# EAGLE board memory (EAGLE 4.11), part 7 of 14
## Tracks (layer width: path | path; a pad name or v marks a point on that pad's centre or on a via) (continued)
AND+TAD+ISZ  (via drill 0.61) (continued)
  Top 0.254: A08.J2 407.67,386.72 407.67,381.64 A08.L2 407.67,380.37 406.4,379.1 406.4,358.14 404.5,356.24 v404.5,346.71 | v428.62,272.42 v428.62,180.97 | v352.43,301.62 v352.43,278.13 | v368.94,345.44 368.3,344.81 v368.3,323.85
  Route2 0.254: v352.43,301.62 352.43,305.44 351.15,306.71 350.52,306.71 349.25,305.44 344.81,305.44 B13.N2
  Route3 0.254: v347.98,316.87 346.07,314.96 346.07,307.34 344.81,306.07 344.81,305.44 B13.N2
  Bottom 0.254: v428.62,180.97 433.07,180.97 D06.J2 | v428.62,272.42 426.08,274.96 403.86,274.96 403.23,275.59 384.81,275.59 384.18,274.96 382.27,274.96 380.37,276.86 366.39,276.86 365.76,277.5 353.06,277.5 v352.43,278.13 | v352.43,301.62 347.98,301.62 B13.P2 | v404.5,346.71 403.23,345.44 v368.94,345.44 | v368.3,323.85 367.67,323.22 365.12,323.22 363.86,321.95 354.96,321.95 354.33,322.58 353.69,322.58 v347.98,316.87
AND+TAD+OP1+JMP  (via drill 0.61)
  Top 0.254: F15.U2 321.94,15.88 319.4,13.34 F15.V2 318.77,12.06 318.77,9.52 317.5,8.25 314.32,8.25 v314.32,22.86 | v353.69,257.18 v357.5,253.36 | v295.27,189.86 295.27,207.64 292.1,210.82 v292.1,228.6
  Route2 0.254: v300.36,260.35 302.26,262.25 311.79,262.25 312.42,261.62 314.96,261.62 318.77,265.43 326.39,265.43 330.2,261.62 337.82,261.62 341,258.44 349.88,258.44 350.52,259.08 351.79,259.08 v353.69,257.18 | v357.5,253.36 358.14,252.73 365.76,252.73 367.03,251.46 369.57,251.46 C11.J2 | v293.37,104.77 v309.25,88.9
  Route3 0.254: v299.72,320.68 301.62,318.77 301.62,279.4 298.45,276.23 298.45,262.25 | 298.45,262.25 v300.36,260.35 | v314.32,22.86 315.6,24.13 315.6,26.67 314.32,27.94 314.32,58.42 308.61,64.13 308.61,65.41 307.98,66.04 307.98,87.63 v309.25,88.9 | v293.37,104.77 292.1,106.04 292.1,116.2 293.37,117.47 293.37,118.74 288.93,123.19 288.93,144.14 285.75,147.32 285.75,170.81 295.27,180.34 v295.27,189.86 | v292.1,228.6 295.27,228.6 295.27,245.11 296.55,246.38 298.45,246.38 298.45,262.25
  Bottom 0.254: v299.72,320.68 297.18,320.68 B17.H2
B_RUN
  Route3 0.254: F36.S2 55.24,22.86 53.98,24.13 53.98,67.31 44.45,76.83 44.45,90.17 43.18,91.44 E37.S2
BM  (via drill 0.61)
  Top 0.254: v224.79,90.8 225.43,91.44 v225.43,122.55 | v207.65,119.38 207.65,123.19 E24.E2
  Bottom 0.254: v224.79,90.8 219.07,90.8 217.81,89.53 E23.T2 | v225.43,122.55 215.26,122.55 214.63,121.92 213.36,121.92 212.09,123.19 208.28,123.19 E24.E2 | v207.65,119.38 200.66,112.39 194.31,112.39 187.96,106.04 179.07,106.04 175.26,109.85 166.37,109.85 162.56,106.04 156.84,106.04 156.21,106.68 150.5,106.68 149.86,106.04 140.97,106.04 137.16,109.85 134.62,109.85 133.99,109.22 125.09,109.22 124.46,109.85 121.92,109.85 121.28,109.22 112.39,109.22 111.76,109.85 109.22,109.85 108.58,109.22 99.69,109.22 99.06,109.85 90.17,109.85 83.19,102.87 74.3,102.87 70.48,106.68 61.59,106.68 60.96,106.04 53.98,106.04 52.7,107.31 E36.L2
BMA0
  Bottom 0.254: F29.D2 141.6,57.79 142.88,59.05 149.86,59.05 150.5,58.42 159.38,58.42 160.02,59.05 162.56,59.05 163.19,58.42 172.09,58.42 172.72,59.05 175.26,59.05 175.9,58.42 184.78,58.42 185.42,59.05 187.96,59.05 188.59,58.42 197.49,58.42 198.12,59.05 199.39,59.05 201.29,57.15 204.47,57.15 F24.D2
BMA1
  Bottom 0.254: F29.E2 144.78,53.34 145.41,52.7 149.86,52.7 150.5,52.07 159.38,52.07 160.02,52.7 162.56,52.7 163.19,52.07 172.09,52.07 172.72,52.7 175.26,52.7 175.9,52.07 184.78,52.07 185.42,52.7 187.96,52.7 188.59,52.07 197.49,52.07 198.12,52.7 200.66,52.7 201.93,51.44 204.47,51.44 F24.F2
BMA2
  Bottom 0.254: F29.H2 144.78,46.99 145.41,46.36 149.86,46.36 150.5,45.72 159.38,45.72 160.02,46.36 162.56,46.36 163.19,45.72 172.09,45.72 172.72,46.36 175.26,46.36 175.9,45.72 184.78,45.72 185.42,46.36 187.96,46.36 188.59,45.72 197.49,45.72 198.12,46.36 199.39,46.36 200.66,45.09 204.47,45.09 F24.J2
BMA3
  Bottom 0.254: F29.K2 144.78,40.64 145.41,40.01 149.86,40.01 150.5,39.37 159.38,39.37 160.02,40.01 162.56,40.01 163.19,39.37 172.09,39.37 172.72,40.01 175.26,40.01 175.9,39.37 184.78,39.37 185.42,40.01 187.96,40.01 188.59,39.37 197.49,39.37 198.12,40.01 200.66,40.01 201.93,38.73 204.47,38.73 F24.L2
BMA4
  Bottom 0.254: F29.M2 144.78,34.29 145.41,33.66 149.86,33.66 150.5,33.02 159.38,33.02 160.02,33.66 162.56,33.66 163.19,33.02 172.09,33.02 172.72,33.66 175.26,33.66 175.9,33.02 184.78,33.02 185.42,33.66 187.96,33.66 188.59,33.02 197.49,33.02 198.12,33.66 200.66,33.66 201.93,32.38 204.47,32.38 F24.N2
BMA5
  Bottom 0.254: F29.P2 144.78,27.94 145.41,27.3 149.86,27.3 150.5,26.67 159.38,26.67 160.02,27.3 162.56,27.3 163.19,26.67 172.09,26.67 172.72,27.3 175.26,27.3 175.9,26.67 184.78,26.67 185.42,27.3 187.96,27.3 188.59,26.67 197.49,26.67 198.12,27.3 200.66,27.3 201.93,26.03 204.47,26.03 F24.R2
BMA6  (via drill 0.61)
  Top 0.254: v146.05,4.44 146.05,20.32 144.78,21.59 F29.S2 | v206.38,5.08 206.38,17.14 205.1,18.41 F24.T2
  Bottom 0.254: v146.05,4.44 147.32,3.17 194.31,3.17 196.22,5.08 v206.38,5.08
BMA7  (via drill 0.61)
  Top 0.254: v139.7,50.16 139.7,20.95 140.97,19.69 F29.T2
  Bottom 0.254: v139.7,50.16 139.7,55.25 149.86,55.25 150.5,55.88 159.38,55.88 160.02,55.25 162.56,55.25 163.19,55.88 172.09,55.88 172.72,55.25 175.26,55.25 175.9,55.88 184.78,55.88 185.42,55.25 187.96,55.25 189.23,56.52 191.77,56.52 F25.D2
BMA8  (via drill 0.61)
  Top 0.254: v180.97,13.34 180.97,16.51 184.15,19.69 184.15,23.49 182.25,25.4 186.69,29.84 187.96,29.84 190.5,32.38 190.5,45.72 192.41,47.62 192.41,50.16 F25.F2
  Bottom 0.254: v180.97,13.34 182.25,13.34 182.25,12.06 180.97,10.79 172.72,10.79 172.09,11.43 164.47,11.43 163.83,10.79 142.88,10.79 141.6,12.06 F29.V2
BMA9  (via drill 0.61)
  Top 0.254: v127,45.72 127,55.25 128.27,56.52 F30.D2
  Bottom 0.254: v127,45.72 127,40.01 133.35,40.01 136.53,43.18 146.69,43.18 147.32,42.55 149.86,42.55 150.5,43.18 159.38,43.18 160.02,42.55 162.56,42.55 163.19,43.18 172.09,43.18 172.72,42.55 175.26,42.55 175.9,43.18 184.78,43.18 185.42,42.55 187.96,42.55 189.23,43.82 191.77,43.82 F25.J2
BMA10
  Bottom 0.254: F30.E2 131.44,53.34 131.44,49.53 129.54,49.53 123.83,43.82 123.83,36.83 133.99,36.83 134.62,36.2 137.16,36.2 137.79,36.83 146.69,36.83 147.32,36.2 149.86,36.2 150.5,36.83 159.38,36.83 160.02,36.2 162.56,36.2 163.19,36.83 172.09,36.83 172.72,36.2 175.26,36.2 175.9,36.83 184.78,36.83 185.42,36.2 186.69,36.2 187.96,37.46 191.77,37.46 F25.L2
BMA11  (via drill 0.61)
  Top 0.254: v138.43,31.75 133.35,36.83 133.35,45.72 132.08,46.99 F30.H2
  Bottom 0.254: v138.43,31.75 140.34,29.84 149.86,29.84 150.5,30.48 159.38,30.48 160.02,29.84 162.56,29.84 163.19,30.48 172.09,30.48 172.72,29.84 175.26,29.84 175.9,30.48 184.78,30.48 185.42,29.84 187.96,29.84 189.23,31.12 191.77,31.12 F25.N2
BMB03  (via drill 0.61)
  Route3 0.254: v49.53,146.69 50.8,147.95 50.8,208.28 49.53,209.55 49.53,212.09 50.16,212.72 50.16,220.98 50.8,221.61 50.8,276.86 48.9,278.77 48.9,287.02 47.62,288.29 47.62,322.58 v48.9,323.85
  Bottom 0.254: v49.53,146.69 48.26,145.41 16.51,145.41 15.88,146.05 0.64,146.05 0.64,144.78 13.34,132.08 15.88,132.08 15.88,126.36 5.71,116.2 5.08,116.2 5.08,111.76 E40.K2 | v48.9,323.85 46.99,325.75 41.27,325.75 40.01,324.49 B37.F2
BMB04  (via drill 0.61)
  Route2 0.254: v5.08,161.29 6.35,161.29 6.35,104.14 5.71,103.5 5.08,103.5 5.08,99.06 E40.P2
  Route3 0.254: v5.08,161.29 3.17,163.19 3.17,193.04 6.35,196.22 v6.35,278.13 | v39.37,288.93 41.27,290.83 41.27,309.25 40.01,310.52 B37.L2
  Bottom 0.254: v6.35,278.13 6.99,278.77 11.43,278.77 20.32,287.66 22.86,287.66 23.5,287.02 32.38,287.02 33.02,287.66 35.56,287.66 36.2,287.02 37.47,287.02 v39.37,288.93
BMB05  (via drill 0.61)
  Top 0.254: v36.2,257.81 38.1,259.72 38.1,294 39.37,295.28 39.37,297.81 B37.R2
  Route3 0.254: v5.08,147.32 3.17,145.41 3.17,90.8 1.91,89.53 E40.T2 | v17.14,155.57 19.05,157.48 19.05,226.69 25.4,233.04 25.4,249.56 v24.13,250.82
  Bottom 0.254: v5.08,147.32 8.26,147.32 16.51,155.57 v17.14,155.57 | v24.13,250.82 28.57,255.27 33.66,255.27 v36.2,257.81
BMB06  (via drill 0.61)
  Route2 0.254: v125.73,387.35 127.64,389.25 137.16,389.25 140.97,385.45 149.86,385.45 156.21,391.8 162.56,391.8 163.19,392.43 172.09,392.43 172.72,391.8 175.26,391.8 175.9,392.43 182.25,392.43 191.77,401.96 200.66,401.96 201.29,401.32 210.19,401.32 220.34,411.48 235.59,411.48 245.11,401.96 251.46,401.96 252.09,401.32 260.99,401.32 261.62,401.96 264.16,401.96 264.8,401.32 273.69,401.32 277.5,405.13 286.38,405.13 290.83,400.69 293.37,400.69 A17.D2
  Route3 0.254: v93.34,231.78 95.25,233.68 95.25,290.83 92.08,294 92.08,347.35 117.47,372.75 117.47,379.1 v125.73,387.35
  Bottom 0.254: v93.34,231.78 88.27,226.69 87,226.69 86.36,227.33 77.47,227.33 70.48,220.34 61.59,220.34 60.96,220.98 58.42,220.98 57.78,220.34 51.44,220.34 48.26,217.17 20.95,217.17 2.54,198.75 1.27,198.75 1.27,194.31 D40.D2
BMB07  (via drill 0.61)
  Top 0.254: v267.97,410.21 268.61,410.85 268.61,415.29 272.42,419.1 301.62,419.1 301.62,414.66 309.88,406.4 v309.88,405.13 | v314.96,393.7 317.5,391.16 v317.5,383.54
  Route2 0.254: v180.97,408.94 180.97,411.48 190.5,411.48 v191.77,410.21
  Route3 0.254: v127,186.69 127,239.39 128.27,240.66 128.27,242.57 127,243.84 127,261.62 125.73,262.89 125.73,264.8 127,266.06 127,270.51 126.36,271.15 126.36,271.78 127,272.42 127,307.34 136.53,316.87 136.53,353.7 146.05,363.22 146.05,369.57 154.94,378.46 154.94,379.73 180.97,405.77 v180.97,408.94 | v309.88,405.13 311.15,403.86 311.15,397.51 v314.96,393.7 | v317.5,383.54 300.36,366.4 299.72,366.4 v297.18,368.94
  Bottom 0.254: v127,186.69 125.73,186.69 123.83,184.78 121.28,184.78 120.65,185.42 116.84,185.42 113.67,182.25 112.39,182.25 111.76,182.88 109.22,182.88 108.58,182.25 99.69,182.25 95.89,186.06 87,186.06 83.19,182.25 74.3,182.25 73.66,182.88 71.12,182.88 70.48,182.25 61.59,182.25 60.96,182.88 58.42,182.88 57.78,182.25 48.9,182.25 48.26,182.88 45.72,182.88 45.09,182.25 36.2,182.25 35.56,182.88 26.67,182.88 22.86,179.07 13.97,179.07 10.16,182.88 5.71,182.88 5.08,183.51 D40.H2 | v191.77,410.21 192.41,410.85 197.49,410.85 198.12,411.48 199.39,411.48 200.66,412.75 248.28,412.75 249.56,411.48 266.06,411.48 267.33,410.21 v267.97,410.21 | v297.18,368.94 294,368.94 A17.R2
BMB08  (via drill 0.61)
  Top 0.254: v238.12,410.21 238.12,396.24 v240.66,393.7 | v299.72,372.75 301.62,370.84 301.62,365.76 v300.99,365.12
  Route2 0.254: v157.48,419.1 155.57,419.1 154.94,419.74 149.22,419.74 145.41,415.93 46.35,415.93 9.53,379.1 6.35,379.1 6.35,307.34 3.17,304.17 3.17,280.04 6.35,276.86 6.35,247.01 2.54,243.2 2.54,240.03 6.35,236.22 6.35,189.86 5.71,189.23 3.17,189.23 3.17,175.26 4.45,173.99 4.45,172.09 D40.M2
  Route3 0.254: v157.48,419.1 161.93,414.66 193.04,414.66 194.31,413.39 238.12,413.39 v238.12,410.21 | v240.66,393.7 241.94,394.97 247.65,394.97 247.65,393.06 257.81,382.91 264.16,382.91 264.8,382.27 273.69,382.27 274.32,382.91 276.86,382.91 277.5,382.27 286.38,382.27 287.02,382.91 289.56,382.91 v299.72,372.75 | v300.99,365.12 297.18,361.31 294,361.31 A17.T2
BPAR
  Route3 0.254: F36.V2 52.07,13.34 50.8,14.61 50.8,69.22 41.27,78.74 41.27,86.99 40.01,88.27 E37.T2
BT00  (via drill 0.61)
  Top 0.254: E09.H2 398.14,118.11 398.14,123.19 E09.E2 | 196.85,299.72 196.85,288.29 195.58,287.02 v195.58,276.23 195.58,274.96 196.85,273.69 v196.85,118.74 196.85,85.09 195.58,83.82 195.58,81.91 196.85,80.64 196.85,17.78 195.58,16.51 F25.U2 | 196.85,299.72 195.58,300.99 B25.P2 | v139.7,276.23 139.7,309.25 140.97,310.52 B29.L2 | 196.85,299.72 196.85,318.77 195.58,320.04 B25.H2 | v203.2,361.95 203.2,398.15 204.47,399.42 A24.D2
  Route2 0.254: v372.75,113.66 372.11,113.03 364.49,113.03 358.14,106.68 351.79,106.68 347.98,102.87 339.09,102.87 335.28,106.68 326.39,106.68 325.75,106.04 325.12,106.04 324.49,106.68 313.69,106.68 313.06,106.04 304.17,106.04 297.18,113.03 288.29,113.03 287.65,112.39 285.12,112.39 v284.48,113.03
  Route3 0.254: v203.2,361.95 201.93,360.68 203.2,359.41 203.2,331.47 195.58,323.85 195.58,321.31 B25.H2 | v255.27,112.39 251.46,116.2 v248.92,116.2
  Bottom 0.254: v195.58,276.23 v139.7,276.23 | v372.75,113.66 374.01,113.66 375.29,112.39 376.56,112.39 378.46,114.3 379.1,114.3 381,112.39 389.25,112.39 389.89,113.03 398.14,113.03 398.14,116.84 E09.H2 | v284.48,113.03 275.59,113.03 274.95,112.39 267.33,112.39 266.06,113.66 264.16,113.66 262.89,112.39 v255.27,112.39 | v248.92,116.2 248.28,115.57 237.49,115.57 233.68,119.38 224.79,119.38 224.16,118.74 215.26,118.74 214.63,119.38 212.09,119.38 211.46,118.74 209.55,118.74 207.65,120.65 207.01,120.65 205.74,119.38 199.39,119.38 198.75,118.74 v196.85,118.74
BT12  (via drill 0.61)
  Top 0.254: v245.11,323.85 245.75,324.49 245.75,326.39 B21.E2
  Route2 0.254: v99.69,309.88 96.52,306.71 92.08,306.71 90.81,305.44 B33.N2 | v147.96,314.33 149.86,316.23 159.38,316.23 160.02,315.6 162.56,315.6 163.19,316.23 172.09,316.23 172.72,315.6 175.26,315.6 175.9,316.23 184.78,316.23 185.42,315.6 187.96,315.6 188.59,316.23 197.49,316.23 201.29,312.42 210.19,312.42 217.17,319.41 226.06,319.41 226.69,318.77 227.33,318.77 228.6,320.04 231.78,320.04 232.41,319.41 238.76,319.41 239.4,318.77 240.03,318.77 v245.11,323.85
  Bottom 0.254: v99.69,309.88 108.58,309.88 109.22,309.25 111.76,309.25 115.57,313.06 124.46,313.06 125.09,312.42 133.99,312.42 134.62,313.06 137.16,313.06 137.79,312.42 146.05,312.42 v147.96,314.33
BT(00-06)  (via drill 0.61)
  Route2 0.254: v300.36,314.33 302.26,312.42 311.79,312.42 312.42,313.06 313.69,313.06 318.13,308.61 321.94,308.61 B15.M2
  Route3 0.254: v233.04,374.02 231.78,372.75 v231.78,372.11 | v271.78,367.67 273.05,366.4 273.05,353.7 274.32,352.43 274.32,338.46 273.05,337.19 273.05,328.3 v284.48,316.87
  Bottom 0.254: v233.04,374.02 231.14,375.92 226.69,375.92 226.06,376.56 223.52,376.56 222.88,375.92 214,375.92 210.82,379.1 206.38,379.1 205.1,380.37 A24.L2 | v231.78,372.11 231.78,370.21 238.76,370.21 239.4,369.57 248.28,369.57 248.92,370.21 251.46,370.21 252.09,369.57 260.99,369.57 261.62,370.21 264.16,370.21 264.8,369.57 269.88,369.57 v271.78,367.67 | v284.48,316.87 285.75,315.6 289.56,315.6 290.19,316.23 291.46,316.23 294.64,313.06 298.45,313.06 299.72,314.33 v300.36,314.33
BT(07-11)  (via drill 0.61)
  Top 0.254: v393.7,245.11 393.7,241.94 394.97,240.66 394.97,238.76 C09.N2
  Bottom 0.254: v393.7,245.11 392.43,245.11 391.16,246.38 386.71,246.38 386.08,247.01 C10.K2
C  (via drill 0.61)
  Route2 0.254: v165.74,344.17 167,345.44 186.69,345.44 187.32,344.81 219.07,344.81 220.34,346.08 254.63,346.08 255.27,345.44 259.71,345.44 v261.62,347.35
  Route3 0.254: v165.74,344.17 161.93,340.36 161.93,310.52 158.75,307.34 158.75,303.53 157.48,302.26 B28.P2 | v261.62,347.35 262.89,348.62 262.89,354.33 269.88,361.31 269.88,367.03 274.32,371.48 v274.95,371.48
  Bottom 0.254: v274.95,371.48 276.86,373.38 286.38,373.38 287.02,372.75 289.56,372.75 290.83,374.02 293.37,374.02 A17.N2
CA  (via drill 0.61)
  Top 0.254: A22.L2 230.5,381.64 231.78,382.91 231.78,391.8 230.5,393.06 A22.F2 | v160.66,279.4 160.66,281.31 154.31,287.66 154.31,291.47 B28.T2 | 206.38,315.6 v206.38,279.4 | 206.38,315.6 205.1,316.87 B24.J2 | 206.38,315.6 206.38,325.12 207.65,326.39 B24.E2
  Route2 0.254: v224.16,377.83 226.06,379.73 229.24,379.73 229.87,380.37 A22.L2
  Route3 0.254: v224.16,377.83 212.72,366.4 212.72,357.5 215.26,354.97 215.26,342.9 209.55,337.19 209.55,328.93 208.28,327.66 B24.E2
  Bottom 0.254: v160.66,279.4 161.93,280.67 197.49,280.67 198.75,279.4 v206.38,279.4
CLL  (via drill 0.61)
  Top 0.254: v396.88,22.86 396.88,29.21 405.13,37.46 407.67,37.46 F08.L2 | v217.17,241.94 215.9,240.66 215.9,235.59 217.17,234.31 217.17,233.68 215.9,232.41 215.9,224.79 217.81,222.88 v217.81,220.98 | v125.73,168.28 123.83,166.37 123.83,147.95 122.56,146.69 v122.56,136.53 | v182.88,75.56 184.15,74.29 v184.15,53.98
  Route2 0.254: v214.63,208.91 214,209.55 201.93,209.55 199.39,212.09 186.69,212.09 181.61,207.01 156.84,207.01 142.24,192.41 137.79,192.41 v128.27,182.88 | v122.56,136.53 130.18,128.91 130.18,125.73 129.54,125.73 124.46,120.65 124.46,119.38 127.64,119.38 167.64,79.38 179.07,79.38 v182.88,75.56 | v184.15,53.98 184.78,53.34 187.32,53.34 194.31,46.36 200.66,46.36 204.47,42.55 213.36,42.55 214,43.18 222.88,43.18 229.87,36.2 238.76,36.2 239.4,36.83 248.28,36.83 252.09,33.02 260.99,33.02 261.62,33.66 264.16,33.66 265.43,32.38 267.97,32.38 F19.N2
  Route3 0.254: v278.76,25.4 273.05,31.12 273.05,31.75 268.61,31.75 F19.N2 | v309.88,26.67 311.15,25.4 311.15,24.13 v313.06,22.23 | v217.17,241.94 219.07,243.84 219.07,249.56 228.6,259.08 228.6,274.96 231.14,277.5 231.14,280.67 228.6,283.21 228.6,300.36 231.78,303.53 231.78,353.06 244.47,365.76 244.47,382.27 245.75,383.54 A21.K2 | v217.81,220.98 219.07,219.71 219.07,216.53 214.63,212.09 v214.63,208.91 | v128.27,182.88 127,181.61 127,169.54 v125.73,168.28
  Bottom 0.254: v278.76,25.4 280.04,24.13 283.85,24.13 287.02,27.3 289.56,27.3 290.19,26.67 299.08,26.67 299.72,27.3 302.26,27.3 302.89,26.67 v309.88,26.67 | v313.06,22.23 314.96,20.32 324.49,20.32 325.12,20.95 326.39,20.95 328.93,18.41 330.2,18.41 331.47,17.14 340.36,17.14 341,17.78 349.88,17.78 350.52,17.14 353.06,17.14 353.69,17.78 362.58,17.78 363.22,17.14 365.76,17.14 366.39,17.78 375.29,17.78 375.92,17.14 378.46,17.14 379.1,17.78 387.99,17.78 388.62,17.14 389.89,17.14 395.61,22.86 v396.88,22.86
CLR_AC  (via drill 0.61)
  Top 0.254: v363.86,79.38 363.22,78.74 v363.22,71.75 | v250.82,24.77 236.85,10.79 233.68,10.79 233.68,15.24 F22.U2
  Route2 0.254: v99.69,25.4 44.45,80.64 44.45,97.79 43.18,97.79 E37.P2 | v363.86,79.38 370.84,79.38 375.92,84.45 377.82,84.45 381.63,80.64 406.4,80.64 406.4,97.79 421.64,113.03 425.45,113.03 425.45,127.63 432.44,134.62 433.07,134.62 433.07,143.51 434.98,145.41 434.98,149.86 434.34,150.5 433.7,150.5 433.7,154.94 D06.T2 | v363.22,71.75 361.31,69.85 342.26,69.85 341.63,70.48 302.89,70.48 v296.55,64.13
  Route3 0.254: v296.55,64.13 282.57,50.16 282.57,43.82 281.94,43.18 275.59,43.18 274.95,42.55 266.7,42.55 266.7,40.64 v250.82,24.77
  Bottom 0.254: v99.69,25.4 104.14,20.95 109.86,20.95 113.67,17.14 122.56,17.14 123.19,17.78 125.73,17.78 126.36,17.14 135.25,17.14 135.89,17.78 138.43,17.78 139.06,17.14 147.96,17.14 148.59,17.78 151.13,17.78 151.76,17.14 160.66,17.14 164.47,20.95 173.35,20.95 173.99,20.32 176.53,20.32 177.16,20.95 186.06,20.95 186.69,20.32 189.23,20.32 189.87,20.95 198.75,20.95 199.39,20.32 201.93,20.32 202.56,20.95 211.46,20.95 212.09,20.32 214.63,20.32 215.26,20.95 224.16,20.95 224.79,20.32 234.95,20.32 234.95,17.78 233.68,16.51 F22.U2
CM
  Top 0.254: E24.P2 207.65,99.06 206.38,100.33 206.38,109.22 205.1,110.49 205.1,113.66 E24.J2
CML  (via drill 0.61)
  Top 0.254: v222.25,294 v222.25,311.15 | v243.21,289.56 244.47,288.29 244.47,154.31 243.21,153.03 v243.21,152.4 | v292.1,144.14 292.1,125.09 295.27,121.92 295.27,116.2 v296.55,114.93 | v328.3,81.28 330.2,79.38 330.2,60.96 v332.11,59.05 | v346.71,46.36 346.07,46.99 346.07,52.07 344.81,53.34 344.81,56.52 F13.D2
  Route2 0.254: v222.25,311.15 217.81,311.15 B23.L2 | v243.21,152.4 249.56,146.05 287.65,146.05 289.56,144.14 v292.1,144.14
  Route3 0.254: v300.36,111.12 301.62,109.85 301.62,84.45 v303.53,82.55 | v367.03,45.09 v369.57,42.55
  Bottom 0.254: v222.25,294 226.06,294 226.69,293.37 235.59,293.37 236.22,294 237.49,294 241.94,289.56 v243.21,289.56 | v296.55,114.93 v300.36,111.12 | v303.53,82.55 304.8,81.28 311.79,81.28 312.42,80.64 327.66,80.64 v328.3,81.28 | v332.11,59.05 339.09,59.05 341,57.15 344.17,57.15 F13.D2 | v369.57,42.55 376.56,42.55 377.19,43.18 379.73,43.18 380.37,42.55 389.25,42.55 389.89,43.18 392.43,43.18 393.06,42.55 401.95,42.55 402.59,43.18 405.13,43.18 405.76,42.55 410.21,42.55 410.85,41.91 F08.K2 | v367.03,45.09 365.76,46.36 354.96,46.36 354.33,45.72 351.79,45.72 351.15,46.36 v346.71,46.36
DC  (via drill 0.61)
  Top 0.254: v82.55,293.37 82.55,318.77 83.82,320.04 v83.82,320.68 | v78.74,341.63 79.38,342.27 79.38,366.4 78.11,367.67 A34.R2 | v370.2,182.88 369.57,183.51 369.57,185.42 365.12,189.86 v365.12,216.53 | v322.58,257.81 320.68,259.72 320.68,266.06 311.15,275.59 v311.15,288.93 | v114.94,290.83 122.56,283.21 v122.56,274.96 | v186.69,278.13 190.5,274.32 v190.5,256.54
  Route2 0.254: v82.55,293.37 82.55,287.66 86.36,287.66 90.81,283.21 104.14,283.21 111.76,290.83 v114.94,290.83 | v122.56,274.96 125.73,278.13 177.16,278.13 178.44,279.4 185.42,279.4 v186.69,278.13 | v190.5,256.54 191.77,255.27 200.66,255.27 204.47,259.08 213.36,259.08 214,258.44 222.88,258.44 223.52,259.08 224.79,259.08 228.6,255.27 234.95,255.27 238.12,252.09 248.28,252.09 255.27,259.08 264.16,259.08 267.97,255.27 276.86,255.27 280.67,259.08 288.93,259.08 292.1,255.91 295.27,255.91 297.18,257.81 302.89,252.09 303.53,252.09 v306.07,254.63
  Route3 0.254: v83.82,320.68 82.55,321.95 82.55,335.92 78.74,339.73 v78.74,341.63 | v325.75,221.61 323.85,223.52 323.85,256.54 v322.58,257.81 | v311.15,288.93 311.15,306.07 309.88,307.34 B16.M2
  Bottom 0.254: v82.55,293.37 74.3,293.37 73.66,294 66.67,294 65.41,292.74 B35.T2 | v370.2,182.88 376.56,182.88 380.37,179.07 389.25,179.07 390.52,180.34 393.06,180.34 394.33,179.07 401.95,179.07 402.59,179.7 405.13,179.7 405.76,179.07 414.65,179.07 415.93,180.34 420.37,180.34 D07.J2 | v365.12,216.53 351.15,216.53 350.52,217.17 336.55,217.17 334.01,219.71 334.01,220.98 329.56,220.98 328.93,220.34 327.02,220.34 v325.75,221.61 | v306.07,254.63 309.88,258.44 311.79,258.44 312.42,259.08 314.96,259.08 315.6,258.44 321.94,258.44 v322.58,257.81
DCA  (via drill 0.61)
  Top 0.254: v235.59,46.36 234.95,46.99 234.95,61.59 v233.04,63.5 | v229.87,65.41 229.87,79.38 225.43,83.82 225.43,88.27 228.6,91.44 228.6,139.06 225.43,142.24 v225.43,210.19 | v434.98,208.91 434.98,273.05 428.62,279.4 v428.62,365.12
  Route2 0.254: v233.04,63.5 231.14,65.41 v229.87,65.41 | v428.62,365.12 427.36,366.4 420.37,366.4 416.56,370.21 410.21,370.21 398.14,382.27 391.8,382.27 388.62,385.45 384.18,385.45 382.9,386.72 A10.J2
  Bottom 0.254: v235.59,46.36 236.85,46.36 240.03,43.18 246.38,43.18 250.19,39.37 254.63,39.37 255.27,38.73 F20.L2 | v225.43,210.19 234.31,210.19 235.59,211.45 314.96,211.45 315.6,210.82 332.11,210.82 332.74,210.19 380.37,210.19 381,209.55 431.17,209.55 431.8,208.91 v434.98,208.91 | v428.62,365.12 428.62,369.57 431.8,369.57 433.7,371.48 436.25,371.48 A06.P2
DF0  (via drill 0.61)
  Top 0.254: v368.3,12.06 360.68,4.44 341.63,4.44 v341.63,12.7 | v338.45,15.88 336.55,15.88 336.55,14.61 333.38,11.43 333.38,9.52 326.39,2.54 326.39,1.27 292.74,1.27 v292.74,5.71 | v252.09,5.71 250.82,4.44 235.59,4.44 235.59,5.71 231.78,9.52 v230.5,9.52
  Route2 0.254: v389.25,7.62 390.52,8.89 391.8,8.89 392.43,8.25 456.56,8.25 478.79,30.48 487.05,30.48 487.05,34.29 F02.M2
  Route3 0.254: v389.25,7.62 388.62,8.25 388.62,8.89 386.71,10.79 368.3,10.79 v368.3,12.06 | v341.63,12.7 v338.45,15.88 | v292.74,5.71 287.02,5.71 285.12,7.62 252.09,7.62 v252.09,5.71 | v230.5,9.52 229.24,8.25 206.38,8.25 206.38,13.97 165.1,55.25 165.1,67.31 149.22,83.18 149.22,91.44 142.88,97.79 142.88,102.23 v140.97,104.14
  Bottom 0.254: v140.97,104.14 138.43,106.68 135.89,106.68 135.25,106.04 126.36,106.04 125.73,106.68 123.19,106.68 121.92,105.41 119.38,105.41 E31.M2
DF1  (via drill 0.61)
  Top 0.254: v187.96,31.12 187.32,31.75 v187.32,74.93
  Route2 0.254: v187.96,31.12 188.59,31.12 189.87,29.84 198.75,29.84 199.39,30.48 201.93,30.48 202.56,29.84 211.46,29.84 212.09,30.48 214.63,30.48 215.26,29.84 224.16,29.84 224.79,30.48 227.33,30.48 227.97,29.84 236.85,29.84 237.49,30.48 246.38,30.48 247.65,29.21 248.92,29.21 251.46,26.67 255.91,26.67 256.54,27.3 263.52,27.3 267.33,23.49 274.95,23.49 278.76,27.3 287.65,27.3 288.29,26.67 290.83,26.67 291.46,27.3 300.36,27.3 300.99,26.67 307.34,26.67 310.51,23.49 313.69,23.49 317.5,27.3 325.75,27.3 332.11,20.95 338.45,20.95 339.09,20.32 341.63,20.32 342.26,20.95 351.15,20.95 351.79,20.32 354.33,20.32 354.96,20.95 363.86,20.95 364.49,20.32 372.11,20.32 375.29,17.14 376.56,17.14 377.19,17.78 386.08,17.78 389.89,13.97 392.43,13.97 393.06,14.61 402.59,14.61 406.4,10.79 454.02,10.79 480.06,36.83 483.24,36.83 483.87,37.46 F02.L2 | v187.32,74.93 186.69,74.29 179.71,74.29 175.26,78.74 140.97,78.74 121.92,97.79 119.38,97.79 E31.P2
DF2  (via drill 0.61)
  Top 0.254: v125.73,120.65 123.83,118.74 123.83,99.69 119.38,95.25 119.38,92.71 E31.S2
  Route2 0.254: v363.22,28.58 363.86,28.58 365.76,26.67 367.03,26.67 367.67,27.3 376.56,27.3 377.19,26.67 387.35,26.67 391.16,30.48 400.05,30.48 403.86,26.67 411.48,26.67 415.29,30.48 424.81,30.48 428.62,26.67 436.88,26.67 440.69,30.48 449.58,30.48 453.39,26.67 464.19,26.67 473.71,36.2 478.15,36.2 481.33,39.37 485.77,39.37 487.05,40.64 F02.K2 | v321.94,57.15 317.5,61.59 317.5,67.94 316.87,67.94 316.23,68.58 307.34,68.58 v306.07,67.31 | v284.48,88.9 v274.95,98.42 | v236.22,93.34 235.59,93.98 228.6,93.98 219.71,102.87 212.09,102.87 198.75,116.2 194.31,116.2 170.81,139.7 145.41,139.7 126.36,120.65 v125.73,120.65
  Route3 0.254: v363.22,28.58 361.31,30.48 351.79,30.48 351.15,29.84 342.26,29.84 330.2,41.91 330.2,48.9 v321.94,57.15 | v306.07,67.31 290.83,82.55 288.93,82.55 288.93,83.82 284.48,88.27 v284.48,88.9
  Bottom 0.254: v274.95,98.42 273.05,100.33 262.89,100.33 262.25,99.69 253.37,99.69 252.73,100.33 251.46,100.33 245.11,93.98 237.49,93.98 236.85,93.34 v236.22,93.34
DM  (via drill 0.61)
  Top 0.254: v201.29,121.92 203.2,120.02 203.2,94.61 204.47,93.34 204.47,89.53 E24.T2 | 53.98,122.55 53.98,191.77 52.7,193.04 D36.D2 | 53.98,122.55 53.98,97.16 52.7,95.88 E36.R2 | v54.61,122.55 53.98,122.55
  Bottom 0.254: v201.29,121.92 200.03,123.19 195.58,123.19 E25.E2 194.94,123.19 193.68,121.92 186.69,121.92 182.88,125.73 173.99,125.73 170.18,121.92 161.29,121.92 160.66,122.55 151.76,122.55 147.96,118.74 139.06,118.74 135.25,122.55 133.99,122.55 133.35,121.92 123.19,121.92 122.56,122.55 118.11,122.55 117.47,121.92 110.49,121.92 106.68,125.73 97.79,125.73 93.98,121.92 85.09,121.92 84.45,122.55 75.56,122.55 74.93,121.92 72.39,121.92 71.75,122.55 62.87,122.55 62.23,121.92 59.69,121.92 59.05,122.55 v54.61,122.55
EM  (via drill 0.61)
  Top 0.254: v57.15,74.29 57.15,83.82 55.88,85.09 E36.U2 | v190.5,73.02 v190.5,93.98 | E25.J2 192.41,113.66 193.68,112.39 193.68,100.33 194.94,99.06 E25.P2
  Bottom 0.254: v57.15,74.29 59.05,72.39 145.41,72.39 146.05,73.02 v190.5,73.02 | v190.5,93.98 190.5,97.79 194.94,97.79 E25.P2
EX+DC  (via drill 0.61)
  Top 0.254: v313.06,143.51 313.69,142.88 313.69,135.89 v313.06,135.25 | v344.17,117.47 344.17,114.93 E13.J2 | B25.E2 194.94,326.39 194.94,324.49 193.04,322.58 193.04,318.77 192.41,318.14 B25.J2 191.77,316.87 v191.77,314.96 | B33.H2 93.34,321.31 93.34,326.39 B33.E2 | v230.5,260.99 225.43,266.06 225.43,270.51 v217.81,278.13
  Route2 0.254: v309.88,186.69 307.98,188.59 302.89,188.59 299.72,191.77 295.27,191.77 294,193.04 D17.D2 | v313.06,135.25 313.69,134.62 321.94,134.62 328.3,128.27 337.19,128.27 337.82,128.91 338.45,128.91 346.71,120.65 v347.35,120.65 | v155.57,321.95 154.94,322.58 148.59,322.58 147.96,321.95 139.06,321.95 138.43,322.58 135.89,322.58 135.25,321.95 126.36,321.95 122.56,325.75 113.67,325.75 109.86,321.95 100.97,321.95 100.33,322.58 97.79,322.58 96.52,321.31 93.98,321.31 B33.H2 | v297.18,217.81 291.46,212.09 254,212.09 v249.56,207.64 | v201.29,311.15 199.39,313.06 193.68,313.06 v191.77,314.96
  Route3 0.254: v309.88,186.69 317.5,179.07 317.5,175.26 314.32,172.09 314.32,164.47 318.77,160.02 318.77,157.48 314.32,153.03 314.32,149.86 315.6,148.59 315.6,146.05 v313.06,143.51 | v297.18,217.81 297.18,208.28 295.27,206.38 295.27,195.58 294,194.31 D17.D2 | v249.56,207.64 247.65,209.55 247.65,254.63 v245.75,256.54 | v210.82,279.4 206.38,283.85 206.38,306.07 v201.29,311.15
  Bottom 0.254: v347.35,120.65 v344.17,117.47 | B36.F2 52.7,323.22 53.98,321.95 60.96,321.95 61.59,322.58 70.48,322.58 71.12,321.95 73.66,321.95 74.3,322.58 75.56,322.58 76.2,321.95 86.36,321.95 87,322.58 92.08,322.58 93.34,321.31 B33.H2 | v155.57,321.95 160.66,321.95 161.29,322.58 168.28,322.58 171.45,325.75 173.35,325.75 177.16,321.95 186.06,321.95 191.13,327.03 194.94,327.03 B25.E2 | v245.75,256.54 243.84,258.44 237.49,258.44 236.85,259.08 232.41,259.08 v230.5,260.99 | v217.81,278.13 216.53,279.4 v210.82,279.4
FM  (via drill 0.61)
  Top 0.254: v210.82,92.07 212.72,93.98 v212.72,107.95
  Bottom 0.254: v210.82,92.07 208.91,90.17 201.29,90.17 200.66,90.8 193.68,90.8 192.41,89.53 E25.T2 | v212.72,107.95 217.17,107.95 E23.L2
GND  (via drill 0.61)
  Top 0.635: C37.H2 42.55,254.63 42.55,259.72 C37.E2 42.55,260.99 42.55,266.06 C37.C2 | B29.U2 144.15,289.56 144.15,294.64 B29.S2 | 128.91,295.28 127,297.18 127,302.9 128.27,304.17 B30.N2 | 128.91,295.28 130.18,294 130.18,290.83 131.44,289.56 B30.U2 | 128.91,295.28 127,293.37 127,272.42 126.36,271.78 126.36,269.24 128.27,267.34 131.44,267.34 C30.C2 | B09.V2 395.61,285.12 395.61,272.42 398.14,269.88 398.14,267.34 C09.C2 | B22.N2 230.5,304.17 230.5,301.62 233.04,299.09 233.04,295.91 B22.S2 233.04,294.64 233.04,289.56 B22.U2 233.68,288.29 233.68,276.23 234.95,274.96 234.95,268.61 233.68,267.34 C22.C2 | A19.N2 268.61,375.29 268.61,380.37 A19.L2 267.97,380.37 263.52,380.37 263.52,347.98 264.16,347.35 266.7,347.35 266.7,347.98 271.78,353.06 | A20.N2 255.27,375.29 255.27,380.37 A20.L2 255.91,381.64 255.91,382.27 257.18,383.54 257.18,388.62 258.44,389.89 A20.H2 | v303.53,374.65 301.62,376.56 301.62,392.43 308.61,399.42 308.61,401.96 309.25,402.59 A16.C2 | A19.H2 271.78,391.16 273.05,392.43 273.05,394.34 279.4,400.69 279.4,401.32 280.67,402.59 283.85,402.59 A18.C2 | A36.C2 55.24,402.59 53.98,401.32 53.98,395.61 52.7,394.34 A36.F2 52.07,393.06 50.8,391.8 50.8,381.64 44.45,375.29 40.01,375.29 A37.N2 | B12.E2 360.05,327.66 360.05,332.74 B12.C2 | B11.E2 372.75,327.66 372.75,332.74 B11.C2 | B10.E2 385.44,327.66 385.44,332.74 B10.C2 | 390.52,310.52 v389.89,309.88 | v390.52,323.22 390.52,310.52 | v388.62,301.62 390.52,303.53 390.52,310.52 | B09.E2 398.14,327.66 398.14,332.74 B09.C2 | B38.H2 29.84,321.31 29.84,326.39 B38.E2 29.84,327.66 29.84,332.74 B38.C2 | B39.C2 17.14,332.74 15.88,331.47 15.88,325.75 14.61,324.49 B39.F2 13.97,323.22 13.97,318.14 B39.J2 13.97,316.87 13.97,311.79 B39.L2 13.97,310.52 13.97,305.44 B39.N2 13.97,304.17 13.97,299.09 B39.R2 14.61,297.81 15.88,296.55 15.88,290.83 17.14,289.56 B39.U2 17.14,288.29 17.14,276.86 15.88,275.59 15.88,268.61 17.14,267.34 C39.C2
  Top 0.635: B30.C2 132.08,332.74 133.35,331.47 133.35,322.58 132.08,321.31 B30.H2 | B35.P2 68.58,302.26 68.58,305.44 69.85,306.71 69.85,325.12 68.58,326.39 B35.E2 67.94,327.66 67.94,332.74 B35.C2 | 153.03,363.86 153.67,364.49 153.67,367.67 A28.R2 153.67,368.94 153.67,374.02 A28.N2 | 153.03,363.86 v146.05,356.87 146.05,346.08 147.32,344.81 147.32,338.46 144.78,335.92 144.78,334.01 B29.C2 144.78,332.74 146.05,331.47 146.05,322.58 144.78,321.31 B29.H2 | 153.03,363.86 153.03,363.22 153.67,362.59 A28.T2 | B22.H2 233.68,321.31 233.68,324.49 234.95,325.75 234.95,328.3 233.68,329.56 233.68,332.74 B22.C2 | 273.05,331.47 273.05,325.75 271.78,324.49 271.78,321.31 B19.H2 271.78,320.04 273.05,318.77 273.05,316.87 276.23,313.69 v276.23,302.9 v276.23,287.66 | 273.05,331.47 271.78,332.74 B19.C2 | 271.78,353.06 271.78,342.27 273.05,341 273.05,331.47 | 271.78,353.06 271.78,358.14 A19.U2 | D09.C2 398.78,196.22 398.78,193.04 400.05,191.77 400.05,186.06 398.78,184.78 D09.H2 | C37.N2 40.01,237.49 41.27,236.22 41.27,224.16 42.55,222.88 C37.U2 43.18,221.61 43.18,205.74 44.45,204.47 44.45,198.75 43.18,197.48 D37.C2 42.55,196.22 41.27,194.94 41.27,189.23 | 41.27,189.23 40.01,187.96 D37.F2 | 41.27,189.23 41.27,167 42.55,165.73 D37.P2 | D31.N2 115.57,168.91 115.57,173.99 D31.L2 116.2,175.26 116.2,177.8 118.11,179.7 118.11,182.88 118.75,183.51 D31.H2 119.38,184.78 120.65,186.06 120.65,194.94 119.38,196.22 D31.C2 | C27.U2 170.18,221.61 170.18,205.74 171.45,204.47 171.45,198.75 170.18,197.48 D27.C2 | C25.T2 192.41,224.79 192.41,222.25 194.94,222.25 C25.U2 194.94,221.61 193.68,220.34 193.68,201.93 194.94,200.66 194.94,197.48 D25.C2
  Top 0.635: C22.U2 233.68,221.61 233.68,205.74 234.95,204.47 234.95,198.75 233.68,197.48 D22.C2 | v355.6,98.42 355.6,84.45 356.87,83.18 E12.V2 357.5,81.91 v357.5,66.04 | E05.V2 446.4,81.91 447.68,80.64 447.68,62.23 448.94,60.96 F05.C2 | F29.F2 140.97,50.16 140.97,45.09 F29.J2 140.97,43.82 140.97,38.73 F29.L2 140.97,37.46 140.97,32.38 F29.N2 140.97,31.12 140.97,26.03 F29.R2 141.6,24.77 142.88,23.49 142.88,17.78 144.15,16.51 F29.U2 | F29.C2 144.15,59.69 142.88,58.42 142.88,52.7 141.6,51.44 F29.F2 | F30.U2 131.44,16.51 130.18,17.78 130.18,23.49 128.91,24.77 F30.R2 128.27,26.03 128.27,31.12 F30.N2 128.27,32.38 128.27,37.46 F30.L2 128.27,38.73 128.27,43.82 F30.J2 128.27,45.09 128.27,50.16 F30.F2 128.91,51.44 130.18,52.7 130.18,58.42 | 130.18,58.42 131.44,59.69 F30.C2 | F32.R2 102.87,26.03 102.87,31.12 F32.N2 102.87,32.38 102.87,37.46 F32.L2 102.87,38.73 102.87,43.82 F32.J2 102.87,45.09 102.87,50.16 F32.F2 | 114.3,21.59 115.57,22.86 115.57,24.77 F31.R2 115.57,26.03 115.57,31.12 F31.N2 115.57,32.38 115.57,37.46 F31.L2 115.57,38.73 115.57,43.82 F31.J2 115.57,45.09 115.57,50.16 F31.F2 116.2,51.44 116.2,53.98 117.47,55.25 117.47,58.42 118.75,59.69 F31.C2 | 114.3,21.59 111.12,18.41 111.12,16.51 106.68,16.51 F32.U2 | 114.3,21.59 114.3,16.51 118.75,16.51 F31.U2 | 130.18,58.42 136.53,52.07 136.53,51.44 140.97,51.44 F29.F2 | F23.E2 220.34,54.61 220.34,59.69 F23.C2 | D10.N2 382.9,167.64 384.18,166.37 384.18,160.66 385.44,159.38 D10.S2 385.44,158.11 385.44,153.03 D10.U2 385.44,151.76 384.18,150.5 384.18,133.35 385.44,132.08 385.44,130.81 E10.C2
  Top 0.635: E12.E2 360.05,124.46 360.05,129.54 E12.C2 | E38.C2 29.84,129.54 28.57,128.27 28.57,122.55 27.3,121.28 E38.F2 27.3,120.02 27.3,114.93 E38.J2 26.67,113.66 26.67,108.58 E38.L2 26.67,107.31 26.67,102.23 E38.N2 26.67,100.96 26.67,95.88 E38.R2 27.3,94.61 28.57,93.34 28.57,87.63 29.84,86.36 E38.U2 29.84,85.09 28.57,83.82 28.57,59.69 | E39.U2 17.14,86.36 15.88,87.63 15.88,93.34 14.61,94.61 E39.R2 13.97,95.88 13.97,100.96 E39.N2 13.97,102.23 13.97,107.31 E39.L2 13.97,108.58 13.97,113.66 E39.J2 13.97,114.93 13.97,120.02 E39.F2 14.61,121.28 15.88,122.55 15.88,128.27 17.14,129.54 E39.C2 | E40.U2 4.45,86.36 3.17,87.63 3.17,93.34 1.91,94.61 E40.R2 1.27,95.88 1.27,100.96 E40.N2 1.27,102.23 1.27,107.31 E40.L2 1.27,108.58 1.27,113.66 E40.J2 1.27,114.93 1.27,120.02 E40.F2 1.91,121.28 3.17,122.55 3.17,128.27 4.45,129.54 E40.C2 4.45,130.81 3.17,132.08 3.17,154.31 | 3.17,154.31 4.45,153.03 D40.U2 | 3.17,154.31 3.17,156.84 1.91,158.11 1.91,161.29 D40.R2 1.27,162.56 1.27,167.64 D40.N2 1.27,168.91 1.27,173.99 D40.L2 1.27,175.26 1.27,180.34 D40.J2 1.27,181.61 1.27,186.69 D40.F2 1.91,187.96 3.17,189.23 3.17,194.94 4.45,196.22 D40.C2 | C39.V2 14.61,218.44 15.88,217.17 15.88,198.75 17.14,197.48 D39.C2 | E32.R2 102.87,95.88 102.87,100.96 E32.N2 102.87,102.23 102.87,107.31 E32.L2 102.87,108.58 102.87,113.66 E32.J2 102.87,114.93 102.87,120.02 E32.F2 | D31.U2 119.38,151.76 119.38,139.06 120.65,137.79 120.65,132.08 119.38,130.81 E31.C2 118.75,129.54 117.47,128.27 117.47,125.09 116.2,123.82 116.2,121.28 E31.F2 115.57,120.02 115.57,114.93 E31.J2 115.57,113.66 115.57,108.58 E31.L2 115.57,107.31 115.57,102.23 E31.N2 115.57,100.96 115.57,95.88 E31.R2 116.2,94.61 116.2,92.07 118.11,90.17 118.11,86.99 118.75,86.36 E31.U2
  Top 0.635: E30.U2 131.44,86.36 130.18,87.63 130.18,93.34 128.91,94.61 E30.R2 128.27,95.88 128.27,100.96 E30.N2 128.27,102.23 128.27,107.31 E30.L2 128.27,108.58 128.27,113.66 E30.J2 128.27,114.93 128.27,120.02 E30.F2 128.91,121.28 130.18,122.55 130.18,128.27 131.44,129.54 E30.C2 | 28.57,59.69 29.84,59.69 F38.C2 | 28.57,59.69 26.67,59.69 25.4,58.42 25.4,33.66 26.67,32.38 F38.N2 | 41.27,87.63 42.55,86.36 E37.U2 | 41.27,87.63 41.27,93.34 40.01,94.61 E37.R2 39.37,95.88 39.37,100.96 E37.N2 39.37,102.23 39.37,107.31 E37.L2 39.37,108.58 39.37,113.66 E37.J2 39.37,114.93 39.37,120.02 E37.F2 40.01,121.28 40.01,123.82 41.27,125.09 41.27,128.27 42.55,129.54 E37.C2 | 41.27,87.63 41.27,62.23 42.55,60.96 F37.C2
  Route2 0.635: B27.N2 166.37,305.44 165.74,306.07 161.29,306.07 160.66,306.71 158.75,306.71 158.12,306.07 155.57,306.07 154.94,306.71 151.76,306.71 151.13,306.07 148.59,306.07 147.96,306.71 146.05,306.71 144.78,305.44 141.6,305.44 B29.N2 | v303.53,374.65 306.07,374.65 A16.N2 | v388.62,301.62 386.08,301.62 B10.P2 | B35.L2 65.41,310.52 65.41,306.71 66.04,306.71 67.94,304.8 67.94,302.26 B35.P2 68.58,300.99 68.58,298.45 76.83,290.2 77.47,290.2 77.47,286.39 B34.V2 | v146.05,356.87 142.24,356.87 141.6,356.24 A29.V2 | F01.J2 496.57,45.09 495.94,45.72 491.49,45.72 490.86,46.36 488.95,46.36 488.31,45.72 485.77,45.72 474.98,56.52 474.98,59.69 F03.C2 | v357.5,66.04 360.05,63.5 360.05,60.96 F12.C2 | C37.H2 42.55,253.36 42.55,249.56 41.91,249.56 38.1,245.75 38.1,238.76 39.37,238.76 C37.N2
  Route3 0.635: C27.T2 167,224.79 169.54,222.25 C27.U2
  Bottom 0.635: C40.C2 5.08,266.06 5.71,265.43 10.16,265.43 10.79,264.8 12.7,264.8 13.97,266.06 17.14,266.06 C39.C2 17.78,266.06 20.32,266.06 21.59,264.8 24.13,264.8 24.77,265.43 29.21,265.43 29.84,266.06 C38.C2 30.48,266.06 33.02,266.06 34.29,264.8 36.83,264.8 38.73,266.7 42.55,266.7 C37.C2 43.18,266.7 46.99,266.7 48.9,268.61 50.8,268.61 52.07,267.34 55.24,267.34 C36.C2 55.88,266.06 56.52,265.43 60.96,265.43 61.59,264.8 63.5,264.8 64.77,266.06 67.94,266.06 C35.C2 68.58,266.06 71.12,266.06 72.39,264.8 74.93,264.8 76.83,266.7 80.64,266.7 C34.C2 81.28,266.7 85.09,266.7 87,268.61 88.9,268.61 90.17,267.34 93.34,267.34 C33.C2 93.98,266.06 94.61,265.43 99.06,265.43 99.69,264.8 101.6,264.8 103.5,266.7 106.05,266.7 C32.C2 106.68,266.7 110.49,266.7 112.39,264.8 113.03,264.8 113.67,265.43 118.11,265.43 118.75,266.06 C31.C2 119.38,266.7 123.19,266.7 125.09,264.8 127,264.8 128.91,266.7 131.44,266.7 C30.C2 132.08,266.7 135.89,266.7 137.79,264.8 139.7,264.8 140.97,266.06 144.15,266.06 C29.C2 144.78,266.06 147.32,266.06 148.59,264.8 151.13,264.8 153.03,266.7 156.84,266.7 C28.C2 157.48,266.7 161.29,266.7 163.19,268.61 165.1,268.61 166.37,267.34 169.54,267.34 C27.C2 170.18,266.7 173.99,266.7 175.9,268.61 177.8,268.61 179.07,267.34 182.25,267.34 C26.C2 182.88,266.7 186.69,266.7 188.59,268.61 190.5,268.61 191.77,267.34 194.94,267.34 C25.C2 195.58,266.7 199.39,266.7 201.29,268.61 203.2,268.61 204.47,267.34 207.65,267.34 C24.C2 208.28,266.7 211.46,266.7 213.36,268.61 214.63,268.61 215.26,267.97 219.71,267.97 220.34,267.34 C23.C2 220.98,266.7 224.79,266.7 226.69,264.8 227.97,264.8 229.87,266.7 233.04,266.7 C22.C2 233.68,266.7 237.49,266.7 239.4,268.61 241.3,268.61 242.57,267.34 245.75,267.34 C21.C2 246.38,266.7 249.56,266.7 251.46,268.61 252.73,268.61 253.37,267.97 257.81,267.97 258.44,267.34 C20.C2 259.08,266.7 262.89,266.7 264.8,264.8 266.7,264.8 268.61,266.7 271.14,266.7 C19.C2 271.78,266.7 275.59,266.7 277.5,264.8 279.4,264.8 281.31,266.7 283.85,266.7 C18.C2 284.48,266.7 287.65,266.7 289.56,264.8 290.83,264.8 291.46,265.43 295.91,265.43 296.55,266.06 C17.C2 297.18,266.7 300.99,266.7 302.89,264.8 304.8,264.8 306.7,266.7 309.25,266.7 C16.C2 309.88,266.7 313.69,266.7 315.6,264.8 317.5,264.8 318.77,266.06 321.94,266.06 C15.C2 322.58,266.06 325.12,266.06 326.39,264.8 328.93,264.8 329.56,265.43 334.01,265.43 334.64,266.06 C14.C2 335.28,266.06 337.82,266.06 339.09,264.8 341.63,264.8 342.26,265.43 346.71,265.43 347.35,266.06 C13.C2 347.98,266.7 351.15,266.7 353.06,268.61 354.33,268.61 354.96,267.97 359.41,267.97 360.05,267.34 C12.C2 360.68,267.34 361.31,267.97 365.76,267.97 366.39,268.61 368.3,268.61 369.57,267.34 372.75,267.34 C11.C2 373.38,267.34 375.92,267.34 377.19,268.61 379.73,268.61 381,267.34 385.44,267.34 C10.C2 386.08,266.7 389.89,266.7 391.8,264.8 392.43,264.8 394.33,266.7 398.14,266.7 C09.C2 398.78,266.7 402.59,266.7 404.5,264.8 406.4,264.8 407.67,266.06 410.85,266.06 C08.C2 411.48,266.06 412.12,265.43 416.56,265.43 417.19,264.8 419.1,264.8 420.37,266.06 423.55,266.06 C07.C2 424.18,266.06 426.72,266.06 427.99,264.8 430.53,264.8 431.17,265.43 435.61,265.43 436.25,266.06 C06.C2 436.88,266.7 440.06,266.7 441.96,268.61 443.23,268.61 444.5,267.34 448.94,267.34 C05.C2 449.58,266.06 450.21,265.43 454.66,265.43 455.3,264.8 456.56,264.8 458.47,266.7 461.64,266.7 C04.C2 462.28,266.06 464.82,266.06 466.09,264.8 468.63,264.8 469.26,265.43 473.71,265.43 474.35,266.06 C03.C2
  Bottom 0.635: B31.U2 119.38,288.29 120.02,287.66 124.46,287.66 125.09,287.02 127,287.02 128.27,288.29 131.44,288.29 B30.U2 132.08,288.29 134.62,288.29 135.89,287.02 138.43,287.02 139.06,287.66 143.51,287.66 144.15,288.29 B29.U2 | B31.N2 116.2,304.17 116.84,303.53 121.28,303.53 121.92,302.9 124.46,302.9 125.73,304.17 128.27,304.17 B30.N2 128.91,304.17 133.35,304.17 134.62,302.9 135.25,302.9 135.89,303.53 140.34,303.53 140.97,304.17 B29.N2 | A19.H2 271.14,389.89 270.51,389.25 266.06,389.25 265.43,388.62 262.89,388.62 261.62,389.89 259.08,389.89 A20.H2 | A19.L2 267.97,380.37 267.33,379.73 262.89,379.73 262.25,379.1 260.35,379.1 259.08,380.37 255.91,380.37 A20.L2 | A03.C2 474.35,402.59 471.17,402.59 469.9,401.32 468,401.32 466.09,403.23 462.28,403.23 A04.C2 461.64,402.59 457.2,402.59 455.93,401.32 454.66,401.32 452.75,403.23 449.58,403.23 A05.C2 448.94,402.59 448.31,401.96 443.87,401.96 443.23,401.32 440.69,401.32 439.42,402.59 436.88,402.59 A06.C2 436.25,403.86 433.07,403.86 431.8,405.13 429.89,405.13 429.26,404.5 424.81,404.5 424.18,403.86 A07.C2 423.55,403.23 419.74,403.23 417.83,401.32 415.29,401.32 414.02,402.59 411.48,402.59 A08.C2 410.85,402.59 410.21,401.96 405.76,401.96 405.13,401.32 403.86,401.32 401.95,403.23 398.78,403.23 A09.C2 398.14,402.59 397.51,401.96 393.06,401.96 392.43,401.32 389.89,401.32 388.62,402.59 386.08,402.59 A10.C2 385.44,402.59 382.27,402.59 381,401.32 379.1,401.32 378.46,401.96 374.01,401.96 373.38,402.59 A11.C2 372.75,403.86 369.57,403.86 368.3,405.13 366.39,405.13 364.49,403.23 360.68,403.23 A12.C2 360.05,403.86 359.41,404.5 354.96,404.5 354.33,405.13 351.79,405.13 350.52,403.86 347.98,403.86 A13.C2 347.35,403.86 344.17,403.86 342.9,405.13 341,405.13 340.36,404.5 335.92,404.5 335.28,403.86 A14.C2 334.64,403.86 331.47,403.86 330.2,405.13 328.3,405.13 326.39,403.23 322.58,403.23 A15.C2 321.94,403.86 321.31,404.5 316.87,404.5 316.23,405.13 313.69,405.13 312.42,403.86 309.88,403.86 A16.C2 309.25,402.59 306.07,402.59 304.8,401.32 302.89,401.32 300.99,403.23 297.18,403.23 A17.C2 296.55,403.86 293.37,403.86 292.1,405.13 290.19,405.13 288.29,403.23 284.48,403.23 A18.C2 283.85,403.86 280.67,403.86 279.4,405.13 277.5,405.13 275.59,403.23 271.78,403.23 A19.C2 271.14,402.59 270.51,401.96 266.06,401.96 265.43,401.32 262.89,401.32 261.62,402.59 259.08,402.59 A20.C2 258.44,402.59 255.27,402.59 254,401.32 252.09,401.32 251.46,401.96 247.01,401.96 246.38,402.59 A21.C2 245.75,402.59 245.11,401.96 240.66,401.96 240.03,401.32 238.76,401.32 236.85,403.23 233.68,403.23 A22.C2 233.04,403.86 229.87,403.86 228.6,405.13 226.69,405.13 224.79,403.23 220.98,403.23 A23.C2 220.34,403.86 217.17,403.86 215.9,405.13 214,405.13 212.09,403.23 208.28,403.23 A24.C2 207.65,402.59 204.47,402.59 203.2,401.32 201.29,401.32 200.66,401.96 196.22,401.96 195.58,402.59 A25.C2 194.94,402.59 191.77,402.59 190.5,401.32 188.59,401.32 186.69,403.23 182.88,403.23 A26.C2 182.25,403.86 181.61,404.5 177.16,404.5 176.53,405.13 173.99,405.13 172.72,403.86 170.18,403.86 A27.C2 169.54,403.86 166.37,403.86 165.1,405.13 163.19,405.13 162.56,404.5 158.12,404.5 157.48,403.86 A28.C2 156.84,403.86 153.67,403.86 152.4,405.13 150.5,405.13 148.59,403.23 144.78,403.23 A29.C2 144.15,402.59 143.51,401.96 139.06,401.96 138.43,401.32 135.89,401.32 134.62,402.59 132.08,402.59 A30.C2 131.44,403.86 130.81,404.5 126.36,404.5 125.73,405.13 123.19,405.13 121.92,403.86 119.38,403.86 A31.C2 118.75,403.86 118.11,404.5 113.67,404.5 113.03,405.13 110.49,405.13 109.22,403.86 106.68,403.86 A32.C2 106.05,403.86 102.87,403.86 101.6,405.13 99.69,405.13 99.06,404.5 94.61,404.5 93.98,403.86 A33.C2 93.34,403.86 90.17,403.86 88.9,405.13 87,405.13 85.09,403.23 81.28,403.23 A34.C2 80.64,403.23 76.83,403.23 74.93,401.32 72.39,401.32 71.12,402.59 68.58,402.59 A35.C2 67.94,402.59 67.31,401.96 62.87,401.96 62.23,401.32 59.69,401.32 58.42,402.59 55.88,402.59 A36.C2
  Bottom 0.635: A40.C2 5.08,402.59 5.71,401.96 10.16,401.96 10.79,401.32 12.7,401.32 13.97,402.59 17.14,402.59 A39.C2 17.78,402.59 20.32,402.59 21.59,401.32 24.13,401.32 24.77,401.96 29.21,401.96 29.84,402.59 A38.C2 30.48,402.59 31.11,401.96 35.56,401.96 36.2,401.32 38.1,401.32 39.37,402.59 42.55,402.59 A37.C2 43.18,402.59 43.18,398.78 45.09,398.78 49.53,394.34 52.07,394.34 A36.F2 | A36.P2 55.24,371.48 51.44,371.48 46.35,376.56 45.09,376.56 43.18,374.65 40.01,374.65 A37.N2 | B12.P2 360.68,301.62 364.49,301.62 366.39,299.72 368.3,299.72 370.2,301.62 372.75,301.62 B11.P2 373.38,301.62 376.56,301.62 378.46,299.72 379.73,299.72 381.63,301.62 385.44,301.62 B10.P2 | v389.89,309.88 394.33,309.88 394.97,310.52 B09.L2 | 390.52,325.12 390.52,326.39 386.08,326.39 B10.E2 | 390.52,325.12 v390.52,323.22 | B09.C2 398.78,332.74 401.32,332.74 402.59,331.47 405.13,331.47 405.76,332.11 410.21,332.11 410.85,332.74 B08.C2 411.48,332.74 414.02,332.74 415.29,331.47 417.83,331.47 418.46,332.11 422.91,332.11 423.55,332.74 B07.C2 424.18,332.74 426.72,332.74 427.99,331.47 430.53,331.47 431.8,332.74 436.25,332.74 B06.C2 436.88,332.74 439.42,332.74 440.69,331.47 443.23,331.47 443.87,332.11 448.31,332.11 448.94,332.74 B05.C2 449.58,332.74 452.12,332.74 453.39,331.47 455.93,331.47 456.56,332.11 461.01,332.11 461.64,332.74 B04.C2 462.28,332.74 464.82,332.74 466.09,331.47 468.63,331.47 469.26,332.11 473.71,332.11 474.35,332.74 B03.C2 | 390.52,325.12 392.43,325.12 393.7,326.39 398.14,326.39 B09.E2 | B10.C2 385.44,332.74 382.27,332.74 381,331.47 379.1,331.47 378.46,332.11 374.01,332.11 373.38,332.74 B11.C2 372.75,332.74 369.57,332.74 368.3,331.47 366.39,331.47 365.76,332.11 361.31,332.11 360.68,332.74 B12.C2 360.05,334.01 356.87,334.01 355.6,335.28 353.69,335.28 351.79,333.38 347.98,333.38 B13.C2 347.35,332.74 344.17,332.74 342.9,331.47 341,331.47 340.36,332.11 335.92,332.11 335.28,332.74 B14.C2 334.64,332.74 331.47,332.74 330.2,331.47 328.3,331.47 326.39,333.38 322.58,333.38 B15.C2 321.94,334.01 318.77,334.01 317.5,335.28 315.6,335.28 313.69,333.38 309.88,333.38 B16.C2 309.25,334.01 306.07,334.01 304.8,335.28 302.89,335.28 300.99,333.38 297.18,333.38 B17.C2 296.55,334.01 293.37,334.01 292.1,335.28 290.19,335.28 288.29,333.38 284.48,333.38 B18.C2 283.85,334.01 283.21,334.65 278.76,334.65 278.13,335.28 276.86,335.28 274.95,333.38 271.78,333.38 B19.C2 271.14,334.01 267.97,334.01 266.7,335.28 264.8,335.28 262.89,333.38 259.08,333.38 B20.C2 258.44,334.01 255.27,334.01 254,335.28 252.09,335.28 250.19,333.38 246.38,333.38 B21.C2 245.75,334.01 242.57,334.01 241.3,335.28 239.4,335.28 237.49,333.38 233.68,333.38 B22.C2 233.04,334.01 229.87,334.01 228.6,335.28 226.69,335.28 224.79,333.38 220.98,333.38 B23.C2 220.34,334.01 217.17,334.01 215.9,335.28 214,335.28 212.09,333.38 208.28,333.38 B24.C2 207.65,334.01 204.47,334.01 203.2,335.28 201.29,335.28 199.39,333.38 195.58,333.38 B25.C2 194.94,334.01 191.77,334.01 190.5,335.28 188.59,335.28 186.69,333.38 182.88,333.38 B26.C2 182.25,334.01 179.07,334.01 177.8,335.28 175.9,335.28 173.99,333.38 170.18,333.38 B27.C2 169.54,334.01 166.37,334.01 165.1,335.28 163.19,335.28 161.29,333.38 157.48,333.38 B28.C2 156.84,334.01 153.67,334.01 152.4,335.28 150.5,335.28 148.59,333.38 144.78,333.38 B29.C2 144.15,334.01 140.97,334.01 139.7,335.28 137.79,335.28 135.89,333.38 132.08,333.38 B30.C2 131.44,334.01 130.81,334.65 126.36,334.65 125.73,335.28 123.19,335.28 121.92,334.01 119.38,334.01 B31.C2 118.75,334.01 118.11,334.65 113.67,334.65 113.03,335.28 110.49,335.28 109.22,334.01 106.68,334.01 B32.C2 106.05,334.01 105.41,334.65 100.97,334.65 100.33,335.28 97.79,335.28 96.52,334.01 93.98,334.01 B33.C2 93.34,334.01 92.71,334.65 88.27,334.65 87.63,335.28 85.09,335.28 83.82,334.01 81.28,334.01 B34.C2 80.64,334.01 80.01,334.65 75.56,334.65 74.93,335.28 72.39,335.28 71.12,334.01 68.58,334.01 B35.C2 67.94,334.01 64.77,334.01 63.5,335.28 61.59,335.28 60.96,334.65 56.52,334.65 55.88,334.01 B36.C2 55.24,334.01 54.61,334.65 50.16,334.65 49.53,335.28 46.99,335.28 45.72,334.01 43.18,334.01 B37.C2 42.55,332.74 41.91,332.11 37.47,332.11 36.83,331.47 34.29,331.47 33.02,332.74 30.48,332.74 B38.C2 29.84,332.74 29.21,332.11 24.77,332.11 24.13,331.47 21.59,331.47 20.32,332.74 17.78,332.74 B39.C2 17.14,333.38 13.97,333.38 12.06,331.47 10.79,331.47 10.16,332.11 5.71,332.11 5.08,332.74 B40.C2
